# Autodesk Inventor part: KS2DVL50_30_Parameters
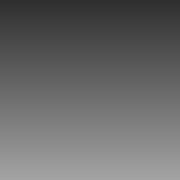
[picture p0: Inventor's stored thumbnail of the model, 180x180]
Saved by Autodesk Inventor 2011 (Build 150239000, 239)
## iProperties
Created: 2010-11
Document SubType Name: Modeling
Designer: TB
Density: 1 g/cm^3
Slaglengde: 100,000 mm
Vinkel_Minusport: 0.00 deg
Forlengelse_rør: 0.000 mm
Minusport2: 180.00 deg
Author: TB
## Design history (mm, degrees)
other parameters: "Slaglengde" = 100 [user parameter], "Forlengelse_rør" = 0 [user parameter], "Vinkel_Minusport" = 0 deg [user parameter], "Minusport2" = 180 deg [user parameter]
